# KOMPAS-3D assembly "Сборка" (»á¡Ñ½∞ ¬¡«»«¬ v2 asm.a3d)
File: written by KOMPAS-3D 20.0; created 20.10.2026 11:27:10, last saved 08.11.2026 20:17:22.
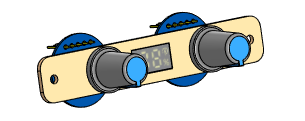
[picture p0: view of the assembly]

Document properties: Полное имя файла: D:\RicWork\Project-EPS32\box_compas\сборки компонентов\панель кнопок v2 asm.a3d

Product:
- Part/product: Сборка
    Масса: 0.0732619
  - Component [assembly]: Сборка  | qty 2  | Масса: 0.0191636; source file: ..\переключатели и кнопки\TZT_EC11 asm.a3d
  - Component [detail]: Деталь  | Масса: 0.027786; source file: ..\корпус\панель кнопоr 2bt.m3d
  - Component [detail]: Деталь  | Масса: 0.00714876; source file: ..\переключатели и кнопки\indicator typa B without button.m3d

Referenced files in D:\RicWork\Project-EPS32\box_compas\переключатели и кнопки\: TZT_EC11 asm.a3d, indicator typa B without button.m3d
Referenced files in D:\RicWork\Project-EPS32\box_compas\корпус\: панель кнопоr 2bt.m3d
